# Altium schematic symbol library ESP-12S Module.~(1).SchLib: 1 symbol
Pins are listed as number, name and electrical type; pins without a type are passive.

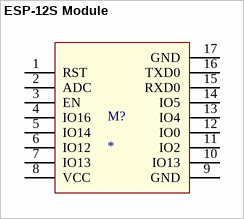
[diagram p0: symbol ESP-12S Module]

## ESP-12S Module
designator M?
ESP-12S Module
footprint ESP-12S Module
pins: 1 RST, 2 ADC, 3 EN, 4 IO16, 5 IO14, 6 IO12, 7 IO13, 8 VCC, 9 GND, 10 IO13, 11 IO2, 12 IO0, 13 IO4, 14 IO5, 15 RXD0, 16 TXD0, 17 GND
